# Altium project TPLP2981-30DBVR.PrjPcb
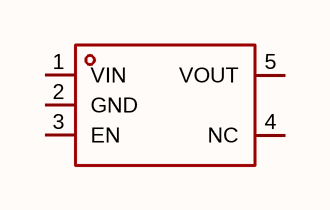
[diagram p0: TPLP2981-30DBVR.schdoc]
1 sheet, 1 parts. Net scope: global (net labels, ports and power ports of the same name join across sheets).

## Sheet TPLP2981-30DBVR.schdoc
size 127 x 101 mm

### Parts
U?  tplp2981-30dbvr  [SOT-23-5_L2.9-W1.6-P0.95-LS2.8-BR]  (value not drawn)

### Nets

Not connected (* = marked no-connect by the designer): U? 1(VIN) 2(GND) 3(EN) 4(NC) 5(VOUT)

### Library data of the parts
U? = tplp2981-30dbvr: 输出极性:正极;工作电压:18V;输出电压:3V;输出电流:100mA;电源纹波抑制比(PSRR):70dB@(1kHz);输出类型:固定;; Manufacturer: TECH PUBLIC(台舟); AddInBom: yes; ModelId: 7ba65df16e7b4570af156e925f9c37fe; ModelTransform: 114.173,114.173,0,90,0,0,0,0,0; Output Configuration: 正极; Voltage - Supply: 18V; Output Voltage: 3V; Output Current: 100mA; Voltage Dropout: 95mV@(100mA); standby current: 20uA; Output Type: 固定; Number of Outputs: 1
